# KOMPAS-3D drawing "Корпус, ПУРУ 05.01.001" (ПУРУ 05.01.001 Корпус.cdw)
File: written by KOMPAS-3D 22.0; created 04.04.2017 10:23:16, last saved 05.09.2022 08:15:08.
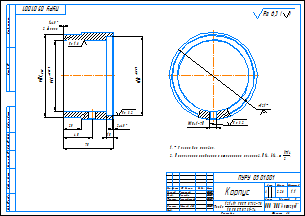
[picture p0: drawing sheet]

Sheet 1: A3, landscape

Document properties: Автор: cons; Полное имя файла: D:\Вован\Антиград\Град\ПУРУ 00.00.000 Установка пусковая ручная Элия-Р\ПУРУ 05.00.000 Корпус\ПУРУ 05.01.000 Обойма\Чертежи\ПУРУ 05.01.001 Корпус.cdw; Масса: 2.255477; Знак неуказанной шероховатости: 4; Параметр неуказанной шероховатости: Ra 6,3

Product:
- Part/product: Корпус  | designation ПУРУ 05.01.001
    Материал: Труба$d121x19 ГОСТ 8732-78;10 ГОСТ 8731-74$ (density 7856 kg/m3)
    Масса: 2.255477
    Раздел спецификации: Детали
    Форматы листов документа: A3
    source file: ..\ПУРУ 05.01.001 Корпус.m3d, ПУРУ 05.01.001 Корпус.cdw
- Part/product: (unnamed)  | designation 1
- Part/product: (unnamed)  | designation 2
- Part/product: (unnamed)  | designation 3

Title block, sheet 1: Наименование: Корпус; designation: ПУРУ 05.01.001; Материал: Труба 121x19 ГОСТ 8732-78 10 ГОСТ 8731-74; Масса: 2,26; Количество листов документа: 1; organisation: ООО "НПЦ"Антиград"; Форматы листов документа: A3; Литера: А; stored path: D:\РУ 00.00.000 Установка противоградовая ручная\РУ 05.00.000 Корпус\РУ 05.01.000 Обойма\Чертежи\РУ 05.01.001 Корпус.cdw; Разработал: Грицунов; Проверил: Налоева; Т. контр.: Семеновский; Н. контр.: Абшаев А.М.; Разработал, date: 06.04.2017; Проверил, date: 06.04.2017; Т. контр., date: 06.04.2017; Н. контр., date: 06.04.2017

Views: Вид 1, Местный разрез 1, Сверху, Проекционный вид 2
Referenced files in D:\Град\ПУРУ 00.00.000 Установка пусковая ручная Элия-Р\ПУРУ 05.00.000 Корпус\ПУРУ 05.01.000 Обойма\: ПУРУ 05.01.001 Корпус.m3d
Referenced files in D:\Вован\Антиград\Град\ПУРУ 00.00.000 Установка пусковая ручная Элия-Р\ПУРУ 05.00.000 Корпус\ПУРУ 05.01.000 Обойма\: ПУРУ 05.01.001 Корпус.m3d
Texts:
  Ra 1,6
  Ra 3,2
  Ra 6,3
  Ra 6,3 ( )
  ПУРУ 05.01.001 Корпус
Dimensions and other numbers on the sheet: 25; 40; 10; 2; 1; 2 фаски; 98; 115; 110; 70; 121; 1:1; 2,26; 06.04.2017

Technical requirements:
  * Размер для справок.
  Неуказанные предельные отклонения размеров: H14, h14,    IT14 2 .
